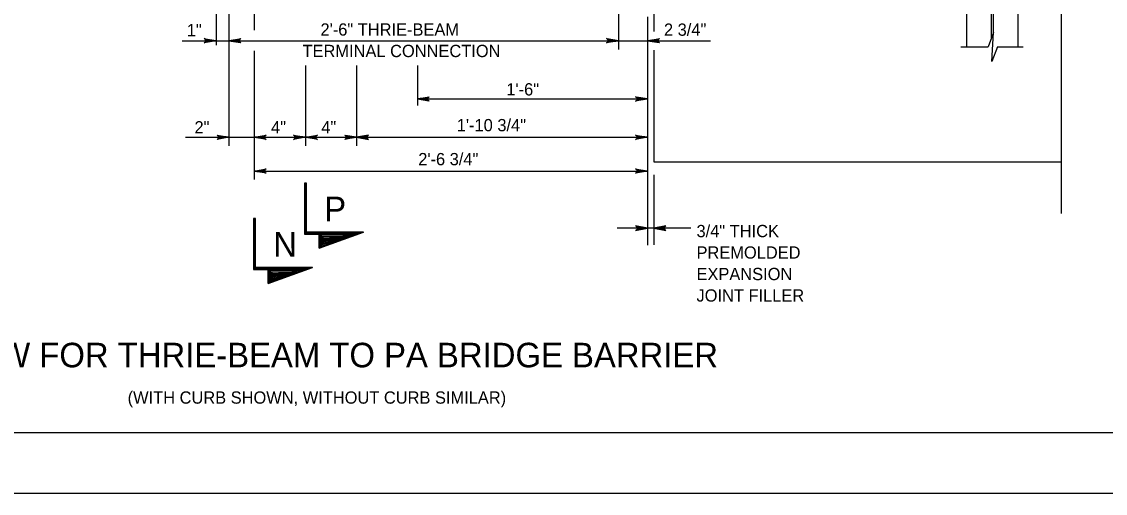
# Model space of a CAD drawing. Extents: x 632007860 to 635435983, y 295418622 to 297794622.
# Drawn here: x 633844963 to 634113990, y 295418622 to 295535766 of the extents above; entities that cross this region are included whole.
import ezdxf

# ---------------------------------------------------------------- set-up
doc = ezdxf.new("R2010")
doc.units = 0
for name, color, linetype in [('1', 7, 'Continuous'), ('PLT-BNDY', 7, 'Continuous'), ('S-DETL-DIMS', 7, 'Continuous'), ('S-DETL-T120', 7, 'Continuous'), ('S-DETL-T240', 7, 'Continuous'), ('S-STEL', 7, 'Continuous')]:
    doc.layers.add(name, color=color, linetype=linetype)

msp = doc.modelspace()

# ---------------------------------------------------------------- linework, layer by layer
at = {"layer": '1'}
msp.add_line((634515860, 295433622), (633729860, 295433622), dxfattribs=at)
at = {"layer": 'PLT-BNDY'}
msp.add_lwpolyline([(633689860, 296012622), (634530860, 296012622), (634530860, 295418622), (633689860, 295418622)], close=True, dxfattribs=at)
at = {"layer": 'S-DETL-DIMS'}
for p, q in [((634103091, 295488138), (634103091, 295580169)), ((633893242, 295572503), (633893242, 295529919)), ((633896417, 295572503), (633896417, 295504931)), ((633993132, 295560314), (633993132, 295528811)), ((633902716, 295553233), (633902716, 295533644)), ((634000348, 295536956), (634000348, 295480242)), ((633884823, 295531044), (634015967, 295531044)), ((633902716, 295528546), (633902716, 295496590)), ((634078116, 295529478), (634084879, 295529478)), ((634087261, 295529478), (634093612, 295529478)), ((633915415, 295524862), (633915415, 295504931)), ((633928117, 295524862), (633928117, 295504931)), ((633943197, 295524862), (633943197, 295514940)), ((633943197, 295516568), (634000348, 295516568)), ((633885671, 295507043), (634000348, 295507043)), ((633902716, 295498661), (634000348, 295498661)), ((634001942, 295497725), (634001942, 295480349)), ((634011116, 295484468), (633992773, 295484468))]:
    msp.add_line(p, q, dxfattribs=at)
for points in [[(633893242, 295531044), (633890283, 295530489), (633890511, 295530647), (633890629, 295530845), (633890663, 295531044), (633890629, 295531242), (633890511, 295531441), (633890283, 295531599), (633893242, 295531044), (633890511, 295531441), (633890629, 295531242), (633893242, 295531044), (633890663, 295531044), (633890629, 295530845), (633893242, 295531044), (633890511, 295530647)], [(633896417, 295531044), (633899377, 295531599), (633899263, 295531520), (633899148, 295531441), (633899090, 295531341), (633899031, 295531242), (633899014, 295531143), (633898997, 295531044), (633899014, 295530945), (633899031, 295530845), (633899090, 295530746), (633899148, 295530647), (633899263, 295530568), (633899377, 295530489), (633896417, 295531044), (633899263, 295530568), (633899148, 295530647), (633896417, 295531044), (633899090, 295530746), (633899031, 295530845), (633896417, 295531044), (633899014, 295530945), (633898997, 295531044), (633896417, 295531044), (633899014, 295531143), (633899031, 295531242), (633896417, 295531044), (633899090, 295531341), (633899148, 295531441), (633896417, 295531044), (633899263, 295531520)], [(633993132, 295531044), (633990172, 295530489), (633990286, 295530568), (633990400, 295530647), (633990459, 295530746), (633990518, 295530845), (633990535, 295530945), (633990552, 295531044), (633990535, 295531143), (633990518, 295531242), (633990459, 295531342), (633990400, 295531441), (633990286, 295531520), (633990172, 295531599), (633993132, 295531044), (633990286, 295531520), (633990400, 295531441), (633993132, 295531044), (633990459, 295531342), (633990518, 295531242), (633993132, 295531044), (633990535, 295531143), (633990552, 295531044), (633993132, 295531044), (633990535, 295530945), (633990518, 295530845), (633993132, 295531044), (633990459, 295530746), (633990400, 295530647), (633993132, 295531044), (633990286, 295530568)], [(634000348, 295531044), (634003307, 295531599), (634003193, 295531520), (634003079, 295531441), (634003020, 295531341), (634002961, 295531242), (634002944, 295531143), (634002927, 295531044), (634002944, 295530945), (634002961, 295530845), (634003020, 295530746), (634003079, 295530647), (634003193, 295530568), (634003307, 295530489), (634000348, 295531044), (634003193, 295530568), (634003079, 295530647), (634000348, 295531044), (634003020, 295530746), (634002961, 295530845), (634000348, 295531044), (634002944, 295530945), (634002927, 295531044), (634000348, 295531044), (634002944, 295531143), (634002961, 295531242), (634000348, 295531044), (634003020, 295531341), (634003079, 295531441), (634000348, 295531044), (634003193, 295531520)], [(634087261, 295529478), (634085811, 295525906), (634086243, 295533050), (634084879, 295529478)], [(633943197, 295516568), (633946157, 295517123), (633946043, 295517044), (633945929, 295516965), (633945870, 295516866), (633945811, 295516766), (633945794, 295516667), (633945777, 295516568), (633945794, 295516469), (633945811, 295516369), (633945870, 295516270), (633945929, 295516171), (633946043, 295516092), (633946157, 295516013), (633943197, 295516568), (633946043, 295516092), (633945929, 295516171), (633943197, 295516568), (633945870, 295516270), (633945811, 295516369), (633943197, 295516568), (633945794, 295516469), (633945777, 295516568), (633943197, 295516568), (633945794, 295516667), (633945811, 295516766), (633943197, 295516568), (633945870, 295516866), (633945929, 295516965), (633943197, 295516568), (633946043, 295517044)], [(634000348, 295516568), (633997388, 295516013), (633997502, 295516092), (633997616, 295516171), (633997675, 295516270), (633997734, 295516369), (633997751, 295516469), (633997768, 295516568), (633997751, 295516667), (633997734, 295516766), (633997675, 295516866), (633997616, 295516965), (633997502, 295517044), (633997388, 295517123), (634000348, 295516568), (633997502, 295517044), (633997616, 295516965), (634000348, 295516568), (633997675, 295516866), (633997734, 295516766), (634000348, 295516568), (633997751, 295516667), (633997768, 295516568), (634000348, 295516568), (633997751, 295516469), (633997734, 295516369), (634000348, 295516568), (633997675, 295516270), (633997616, 295516171), (634000348, 295516568), (633997502, 295516092)], [(633896417, 295507043), (633893458, 295506488), (633893686, 295506646), (633893803, 295506844), (633893838, 295507043), (633893803, 295507241), (633893686, 295507440), (633893458, 295507598), (633896417, 295507043), (633893686, 295507440), (633893803, 295507241), (633896417, 295507043), (633893838, 295507043), (633893803, 295506844), (633896417, 295507043), (633893686, 295506646)], [(633902716, 295507043), (633905675, 295507598), (633905447, 295507440), (633905330, 295507241), (633905296, 295507043), (633905330, 295506844), (633905447, 295506646), (633905675, 295506488), (633902716, 295507043), (633905447, 295506646), (633905330, 295506844), (633902716, 295507043), (633905296, 295507043), (633905330, 295507241), (633902716, 295507043), (633905447, 295507440)], [(633915415, 295507043), (633912456, 295506488), (633912684, 295506646), (633912801, 295506844), (633912835, 295507043), (633912801, 295507241), (633912684, 295507440), (633912456, 295507598), (633915415, 295507043), (633912684, 295507440), (633912801, 295507241), (633915415, 295507043), (633912835, 295507043), (633912801, 295506844), (633915415, 295507043), (633912684, 295506646)], [(633915415, 295507043), (633918374, 295507598), (633918146, 295507440), (633918029, 295507241), (633917995, 295507043), (633918029, 295506844), (633918146, 295506646), (633918374, 295506488), (633915415, 295507043), (633918146, 295506646), (633918029, 295506844), (633915415, 295507043), (633917995, 295507043), (633918029, 295507241), (633915415, 295507043), (633918146, 295507440)], [(633928117, 295507043), (633925158, 295506488), (633925272, 295506567), (633925386, 295506646), (633925445, 295506745), (633925504, 295506844), (633925521, 295506944), (633925538, 295507043), (633925521, 295507142), (633925504, 295507241), (633925445, 295507341), (633925386, 295507440), (633925272, 295507519), (633925158, 295507598), (633928117, 295507043), (633925272, 295507519), (633925386, 295507440), (633928117, 295507043), (633925445, 295507341), (633925504, 295507241), (633928117, 295507043), (633925521, 295507142), (633925538, 295507043), (633928117, 295507043), (633925521, 295506944), (633925504, 295506844), (633928117, 295507043), (633925445, 295506745), (633925386, 295506646), (633928117, 295507043), (633925272, 295506567)], [(633928117, 295507043), (633931077, 295506488), (633930963, 295506567), (633930849, 295506646), (633930790, 295506745), (633930731, 295506844), (633930714, 295506944), (633930697, 295507043), (633930714, 295507142), (633930731, 295507241), (633930790, 295507341), (633930849, 295507440), (633930963, 295507519), (633931077, 295507598), (633928117, 295507043), (633930963, 295507519), (633930849, 295507440), (633928117, 295507043), (633930790, 295507341), (633930731, 295507241), (633928117, 295507043), (633930714, 295507142), (633930697, 295507043), (633928117, 295507043), (633930714, 295506944), (633930731, 295506844), (633928117, 295507043), (633930790, 295506745), (633930849, 295506646), (633928117, 295507043), (633930963, 295506567)], [(634000348, 295507043), (633997388, 295506488), (633997616, 295506646), (633997734, 295506844), (633997768, 295507043), (633997734, 295507241), (633997616, 295507440), (633997388, 295507598), (634000348, 295507043), (633997616, 295507440), (633997734, 295507241), (634000348, 295507043), (633997768, 295507043), (633997734, 295506844), (634000348, 295507043), (633997616, 295506646)], [(633902716, 295498661), (633905675, 295499216), (633905447, 295499058), (633905330, 295498859), (633905296, 295498661), (633905330, 295498462), (633905447, 295498264), (633905675, 295498106), (633902716, 295498661), (633905447, 295498264), (633905330, 295498462), (633902716, 295498661), (633905296, 295498661), (633905330, 295498859), (633902716, 295498661), (633905447, 295499058)], [(634000348, 295498661), (633997388, 295498106), (633997616, 295498264), (633997734, 295498462), (633997768, 295498661), (633997734, 295498859), (633997616, 295499058), (633997388, 295499216), (634000348, 295498661), (633997616, 295499058), (633997734, 295498859), (634000348, 295498661), (633997768, 295498661), (633997734, 295498462), (634000348, 295498661), (633997616, 295498264)], [(633915415, 295495680), (633915415, 295483245), (633929106, 295483245), (633929833, 295483510), (633915679, 295483510), (633915679, 295495680), (633915150, 295495680), (633915150, 295482980), (633928379, 295482980), (633918854, 295479514), (633918854, 295482980), (633929833, 295483510), (633919195, 295479939), (633919172, 295482726), (633927304, 295482818), (633919482, 295480306), (633919482, 295482428), (633925675, 295482520), (633919780, 295480685), (633919792, 295482107), (633924597, 295482348), (633920067, 295481086), (633920078, 295481843), (633923175, 295482095), (633920319, 295481350), (633920354, 295481671), (633922040, 295481866), (633920326, 295481508), (633918854, 295479514), (633918854, 295482980), (633920354, 295481671), (633929833, 295483510)], [(633902758, 295486881), (633902758, 295474445), (633916449, 295474445), (633917176, 295474710), (633903023, 295474710), (633903023, 295486881), (633902493, 295486881), (633902493, 295474181), (633915723, 295474181), (633906198, 295470714), (633906198, 295474181), (633917176, 295474710), (633906538, 295471139), (633906516, 295473926), (633914647, 295474018), (633906825, 295471506), (633906825, 295473628), (633913018, 295473720), (633907123, 295471885), (633907135, 295473307), (633911940, 295473548), (633907410, 295472286), (633907422, 295473043), (633910518, 295473296), (633907662, 295472550), (633907697, 295472871), (633909383, 295473066), (633907669, 295472709), (633906198, 295470714), (633906198, 295474181), (633907697, 295472871), (633917176, 295474710)], [(634000348, 295484468), (633997388, 295485023), (633997502, 295484944), (633997616, 295484865), (633997675, 295484766), (633997734, 295484667), (633997751, 295484567), (633997768, 295484468), (633997751, 295484369), (633997734, 295484270), (633997675, 295484170), (633997616, 295484071), (633997502, 295483992), (633997388, 295483913), (634000348, 295484468), (633997502, 295483992), (633997616, 295484071), (634000348, 295484468), (633997675, 295484170), (633997734, 295484270), (634000348, 295484468), (633997751, 295484369), (633997768, 295484468), (634000348, 295484468), (633997751, 295484567), (633997734, 295484667), (634000348, 295484468), (633997675, 295484766), (633997616, 295484865), (634000348, 295484468), (633997502, 295484944)], [(634001942, 295484468), (634004901, 295483913), (634004787, 295483992), (634004673, 295484071), (634004615, 295484170), (634004556, 295484270), (634004539, 295484369), (634004522, 295484468), (634004539, 295484567), (634004556, 295484667), (634004615, 295484766), (634004673, 295484865), (634004787, 295484944), (634004901, 295485023), (634001942, 295484468), (634004787, 295484944), (634004673, 295484865), (634001942, 295484468), (634004615, 295484766), (634004556, 295484667), (634001942, 295484468), (634004539, 295484567), (634004522, 295484468), (634001942, 295484468), (634004539, 295484369), (634004556, 295484270), (634001942, 295484468), (634004615, 295484170), (634004673, 295484071), (634001942, 295484468), (634004787, 295483992)]]:
    msp.add_lwpolyline(points, dxfattribs=at)
for points in [[(633915679, 295495680), (633915150, 295495680), (633915150, 295482980), (633918854, 295482980), (633918854, 295479514), (633929833, 295483510), (633915679, 295483510)], [(633903023, 295486881), (633902493, 295486881), (633902493, 295474181), (633906198, 295474181), (633906198, 295470714), (633917176, 295474710), (633903023, 295474710)]]:
    msp.add_lwpolyline(points, close=True, dxfattribs=at)
at = {"layer": 'S-STEL'}
for p, q in [((634085623, 295640078), (634085623, 295531427)), ((634086152, 295640078), (634086152, 295532811)), ((634079530, 295551503), (634079530, 295529478)), ((634092245, 295551503), (634092245, 295529478)), ((634001942, 295539008), (634001942, 295533303)), ((634001942, 295528667), (634001942, 295500950)), ((634001942, 295500950), (634103091, 295500950))]:
    msp.add_line(p, q, dxfattribs=at)

# ---------------------------------------------------------------- texts
at = {"layer": 'S-DETL-T120'}
for s, height, p in [('1"', 3048, (633885968, 295532145)), ('2\'-6" THRIE-BEAM', 3048.01, (633919153, 295532299)), ('2 3/4"', 3048, (634004417, 295532262)), ('TERMINAL CONNECTION', 3048.01, (633914689, 295526965)), ('1\'-6"', 3048, (633965294, 295517439)), ('2"', 3048, (633887875, 295508008)), ('4"', 3048, (633906868, 295508007)), ('4"', 3048, (633919344, 295508007)), ('1\'-10 3/4"', 3048, (633952987, 295508545)), ('2\'-6 3/4"', 3048, (633943416, 295500105)), ('3/4" THICK ', 3048.07, (634012496, 295482241)), ('PREMOLDED ', 3048.1, (634012496, 295476907)), ('EXPANSION ', 3048.1, (634012496, 295471573)), ('JOINT FILLER', 3048.07, (634012496, 295466239)), ('(WITH CURB SHOWN, WITHOUT CURB SIMILAR)', 3048.01, (633871271, 295440889))]:
    msp.add_text(s, height=height, dxfattribs=at).set_placement(p)
at = {"layer": 'S-DETL-T240'}
for s, p in [('P', (633920069, 295486202)), ('N', (633907412, 295477402)), ('ELEVATION VIEW FOR THRIE-BEAM TO PA BRIDGE BARRIER', (633778227, 295449918))]:
    msp.add_text(s, height=6096, dxfattribs=at).set_placement(p)

doc.saveas('drawing.dxf')
